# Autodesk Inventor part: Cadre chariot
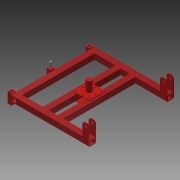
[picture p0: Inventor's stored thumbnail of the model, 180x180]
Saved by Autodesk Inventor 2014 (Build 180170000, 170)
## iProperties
Created: 2015-06
Part Number: Cadre chariot
Material: Générique
Document SubType Name: Modeling
Designer: OL
Density: 1 g/cm^3
Appearance: Par défaut
Author: OL
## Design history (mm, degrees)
sketch "Esquisse1"
  geometry: L1 (-515, 35)-(-445, 35); L2 (-445, 35)-(-445, -35); L3 (-445, -35)-(-515, -35); L4 (-515, -35)-(-515, 35); L5 (-452.5, -27.5)-(-507.5, -27.5); L6 (-507.5, -27.5)-(-507.5, 27.5); L7 (-507.5, 27.5)-(-452.5, 27.5); L8 (-452.5, 27.5)-(-452.5, -27.5); L9 (445, 35)-(515, 35); L10 (515, 35)-(515, -35); L11 (515, -35)-(445, -35); L12 (445, -35)-(445, 35); L13 (507.5, -27.5)-(452.5, -27.5); L14 (452.5, -27.5)-(452.5, 27.5); L15 (452.5, 27.5)-(507.5, 27.5); L16 (507.5, 27.5)-(507.5, -27.5); 1 further point
  constraints: 32 end point, 8 parallel, 4 horizontal, 4 perpendicular
  dimensions: "d0" = 7.5 distance between parallel lines of L14 L12; "d2" = 7.5 distance between parallel lines of L2 L8; "d3" = 890 distance between parallel lines of L12 L2; "d4" = 445 distance from line of L2 point (0, 0) (= 0.5 x d3); "d5" = 70 distance of L1.end L2.end; "d6" = 7.5 distance between parallel lines of L1 L7 (= d2); "d7" = 7.5 distance between parallel lines of L4 L6 (= d2); "d8" = 7.5 distance between parallel lines of L3 L5 (= d2); "d9" = 35 distance from line of point (0, 0) L1; "d10" = 70 distance of L1.start L1.end (= d5); "d11" = 7.5 distance between parallel lines of L9 L15 (= d2); "d12" = 7.5 distance between parallel lines of L11 L13 (= d0); "d13" = 7.5 distance between parallel lines of L10 L16 (= d0); "d14" = 70 distance of L11.end L9.start; "d15" = 35 distance from line of point (0, 0) L9; "d16" = 70 distance of L9.start L9.end (= d14)
extrude "Extrusion1" new body sketch "Esquisse1" distance "d17" = 900; taper "d18" = 0 deg
sketch "Esquisse3"
  geometry: L1 (0, 0)-(-70, 0); L2 (-70, 0)-(-70, 70); L3 (-70, 70)-(0, 70); L4 (0, 70)-(0, 0); L5 (-7.5, 62.5)-(-62.5, 62.5); L6 (-62.5, 62.5)-(-62.5, 7.5); L7 (-62.5, 7.5)-(-7.5, 7.5); L8 (-7.5, 7.5)-(-7.5, 62.5); 1 further point
  constraints: 16 end point, 4 parallel, 2 perpendicular, 1 horizontal, 3 other
  dimensions: "d19" = 70 distance of L2.end L3.end; "d21" = 70 distance between parallel lines of L1 L3; "d22" = 7.5 distance between parallel lines of L2 L6
extrude "Extrusion2" join sketch "Esquisse3" stored distance "d23" = 970; taper "d24" = 0 deg
sketch "Esquisse4"
  geometry: L1 (-900, 0)-(-900, 70) reference; L2 (-900, 0)-(0, 0) reference; L3 (-900, 70)-(0, 70) reference; L4 (-645, 70)-(-575, 70); L5 (-575, 70)-(-575, 0); L6 (-575, 0)-(-645, 0); L7 (-645, 0)-(-645, 70); L8 (-465, 70)-(-395, 70); L9 (-395, 70)-(-395, 0); L10 (-395, 0)-(-465, 0); L11 (-465, 70)-(-465, 0); L12 (-582.5, 7.5)-(-582.5, 62.5); L13 (-582.5, 62.5)-(-637.5, 62.5); L14 (-637.5, 62.5)-(-637.5, 7.5); L15 (-637.5, 7.5)-(-582.5, 7.5); L16 (-457.5, 7.5)-(-402.5, 7.5); L17 (-402.5, 7.5)-(-402.5, 62.5); L18 (-402.5, 62.5)-(-457.5, 62.5); L19 (-457.5, 62.5)-(-457.5, 7.5); 1 further point
  constraints: 32 end point, 6 parallel, 5 perpendicular, 3 point on line, 2 horizontal, 6 other
  dimensions: "d25" = 70 distance of L5.end L6.end; "d28" = 255 distance between parallel lines of L7 L1; "d29" = 110 distance between parallel lines of L5 L11; "d30" = 70 distance between parallel lines of L9 L11; "d31" = 7.5 distance between parallel lines of L5 L12; "d32" = 7.5 distance between parallel lines of L11 L19; "d33" = 70 distance between parallel lines of L10 L8
extrude "Extrusion3" join sketch "Esquisse4" stored distance "d34" = 970; taper "d35" = 0 deg
sketch "Esquisse5"
  geometry: L1 (0, 70)-(0, 0) reference; L2 (0, 70)-(-970, 70) reference; L3 (-80, 60)-(0, 60); L4 (0, 60)-(0, -150); L5 (-20, -170)-(-60, -170); L6 (-80, -150)-(-80, 60); L7 (-80, -150)-(-60, -170); L8 (-20, -170)-(0, -150); C1 r 12.5 at (-40, -130); 1 further point
  constraints: 12 end point, 2 parallel, 1 centre point, 1 horizontal, 1 perpendicular
  dimensions: "d38" = 80 distance of L3.start L3.end; "d39" = 230 distance between parallel lines of L5 L3; "d40" = 20 horizontal distance of L6.start L5.end; "d41" = 20 horizontal distance of L6.start L5.end; "d42" = 20 horizontal distance of L5.start L4.end; "d43" = 20 horizontal distance of L5.start L4.end; "d44" = 10 distance between parallel lines of L2 L3; "d45" = 0 distance between parallel lines of L1 L4; "d46" = 40 distance from line of L5 C1.centre; "d47" = 25 diameter of C1; "d48" = 40 distance from line of L4 C1.centre
extrude "Extrusion4" join sketch "Esquisse5" distance "d49" = 10; taper "d50" = 0 deg
node "Plan de construction1"
mirror "Symétrie1"
mirror "Symétrie2"
sketch "Esquisse6"
  geometry: L1 (575, 960)-(465, 960) reference; L2 (645, 70)-(645, 960) reference; L3 (420, 615)-(620, 615); L4 (620, 615)-(620, 415); L5 (620, 415)-(420, 415); L6 (420, 415)-(420, 615); C1 r 7 at (445, 590); C2 r 7 at (520, 590); C3 r 7 at (595, 590); C4 r 7 at (595, 515); C5 r 7 at (595, 440); C6 r 7 at (520, 440); C7 r 7 at (445, 440); C8 r 7 at (445, 515); C9 r 32.5 at (520, 515); 1 further point
  constraints: 9 centre point, 8 end point, 2 parallel, 1 horizontal, 1 perpendicular
  dimensions: "d52" = 200 distance of L3.start L3.end; "d54" = 200 distance of L5.end L3.start; "d55" = 345 distance between parallel lines of L1 L3; "d56" = 25 distance between parallel lines of L2 L4; "d57" = 14 diameter of C1; "d58" = 14 diameter of C2; "d59" = 14 diameter of C3; "d60" = 14 diameter of C4; "d61" = 14 diameter of C5; "d62" = 14 diameter of C6; "d63" = 14 diameter of C7; "d64" = 14 diameter of C8; "d66" = 25 distance from line of L3 C1.centre; "d67" = 25 distance from line of L3 C2.centre; "d68" = 100 distance from line of L6 C2.centre; "d69" = 25 distance from line of L3 C3.centre; "d72" = 100 distance from line of L5 C4.centre; "d74" = 25 distance from line of L5 C5.centre; "d76" = 100 distance from line of L4 C6.centre; "d77" = 25 distance from line of L5 C7.centre; "d80" = 100 distance from line of L5 C8.centre; "d81" = 65 diameter of C9; "d82" = 100 distance from line of L6 C9.centre; "d83" = 100 distance from line of L5 C9.centre; "d126" = 75 distance of C8.centre C9.centre; "d127" = 75 horizontal distance of C7.centre C9.centre; "d128" = 75 horizontal distance of C1.centre C9.centre; "d129" = 75 horizontal distance of C3.centre C9.centre; "d130" = 75 distance of C4.centre C9.centre; "d131" = 75 horizontal distance of C5.centre C9.centre; "d132" = 75 distance of C9.centre C6.centre
extrude "Extrusion5" join sketch "Esquisse6" distance "d84" = 10; taper "d85" = 0 deg
sketch "Esquisse7"
  geometry: C1 r 32.5 at (520, 515) reference; C2 r 27.5 at (520, 515); 1 further point
  constraints: 1 centre point, 1 coincident
  dimensions: "d86" = 55 diameter of C2
extrude "Extrusion6" join sketch "Esquisse7" distance "d88" = 5; taper "d89" = 0 deg
sketch "Esquisse8"
  geometry: C1 r 27.5 at (0, 0) reference; C2 r 32.5 at (0, 0) reference; 1 further point
  dimensions: "d95" = 65 diameter of C2 (derived); "d96" = 55 diameter of C1 (derived)
extrude "Extrusion7" join sketch "Esquisse8" distance "d90" = 220; taper "d91" = 0 deg
pattern_linear "Réseau rectangulaire1" dims "d94" = 80
sketch "Esquisse9"
  geometry: C1 r 27.5 at (0, 0) reference; 1 further point
extrude "Extrusion8" join sketch "Esquisse9" distance "d97" = 10; taper "d98" = 0 deg
sketch "Esquisse10"
  geometry: L1 (0, 0)-(970, 0) reference; L2 (970, 1030)-(970, 0) reference; L3 (0, 1030)-(970, 1030) reference; L4 (970, 540)-(1020, 540); L5 (1020, 540)-(1020, 490); L6 (1020, 490)-(970, 490); L7 (970, 490)-(970, 540); 1 further point
  constraints: 8 end point, 2 parallel, 1 horizontal, 1 perpendicular, 1 point on line
  dimensions: "d99" = 50 distance of L4.start L4.end; "d101" = 50 distance of L4.end L5.end; "d102" = 490 distance between parallel lines of L3 L4; "d103" = 490 distance between parallel lines of L1 L6 (derived)
extrude "Extrusion9" join sketch "Esquisse10" stored distance "d104" = 18; taper "d105" = 0 deg
sketch "Esquisse11"
  geometry: L1 (-625, 470)-(-575, 470) reference; L2 (-625, 420)-(-625, 470) reference; L3 (-575, 420)-(-625, 420) reference; L4 (0, 0)-(0, 890) reference; L5 (-575, 470)-(-575, 420); 1 further point
  constraints: 2 end point, 1 parallel
extrude "Extrusion10" join sketch "Esquisse11" distance "d106" = 18; taper "d107" = 0 deg
sketch "Esquisse12"
  geometry: L1 (-625, 420)-(-575, 420) reference; L2 (-575, 420)-(-575, 470) reference; C1 r 12.5 at (-600, 445); 1 further point
  constraints: 1 centre point
  dimensions: "d108" = 25 diameter of C1; "d110" = 25 distance from line of L2 C1.centre; "d111" = 25 distance from line of L1 C1.centre
extrude "Extrusion11" join sketch "Esquisse12" distance "d112" = 70; taper "d113" = 0 deg
sketch "Esquisse13"
  geometry: L1 (70, 0)-(70, -490) reference; L2 (0, 0)-(70, 0) reference; L3 (80, -10)-(80, -60); L4 (80, -60)-(-50, -60); L5 (-50, -60)-(-50, -10); L6 (-50, -10)-(80, -10); 2 further points
  constraints: 8 end point, 1 parallel, 1 perpendicular, 1 point on line
  dimensions: "d133" = 130 distance of L3.end L4.end; "d135" = 50 distance between parallel lines of L4 L6; "d136" = 10 distance between parallel lines of L6 L2; "d137" = 10 distance between parallel lines of L3 L1
extrude "Extrusion12" join sketch "Esquisse13" distance "d118" = 50; taper "d119" = 0 deg
sketch "Esquisse14"
  geometry: L1 (50, 50)-(50, 0) reference; L2 (0, 0)-(50, 0) reference; C1 r 12.5 at (25, 25); 1 further point
  constraints: 1 centre point
  dimensions: "d120" = 25 diameter of C1; "d122" = 25 distance from line of L1 C1.centre; "d138" = 25 distance from line of L2 C1.centre
extrude "Extrusion13" cut sketch "Esquisse14" stored distance "d124" = 50; taper "d125" = 0 deg
mirror "Symétrie3"
node "Solide1"
other parameters: "d51" = -35
